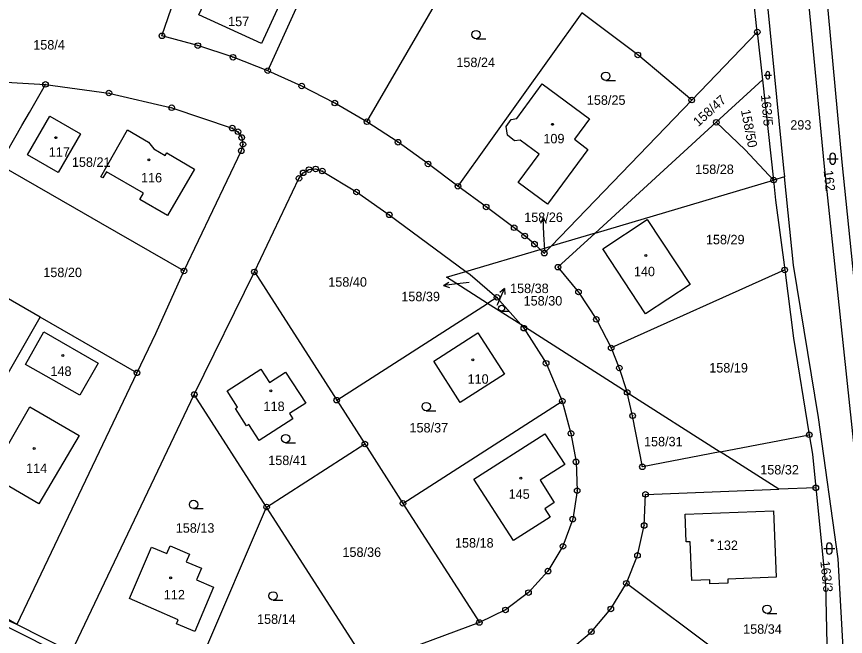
# Model space of a CAD drawing. Extents: x -779723 to -777378, y -1011169 to -1009297.
# Drawn here: x -779372 to -779222.9, y -1010124.4 to -1010012.9 of the extents above; entities that cross this region are included whole.
import ezdxf

# ---------------------------------------------------------------- set-up
doc = ezdxf.new("R2010")
doc.units = 0
for name, color, linetype in [('Hranice parcel', 7, 'Continuous'), ('Parcelní čísla', 7, 'Continuous'), ('Pop  PČ popisy', 7, 'Continuous'), ('Věcná břemena k části', 7, 'Continuous'), ('Značky bodu BP', 7, 'Continuous'), ('Značky budov', 7, 'Continuous'), ('Značky kultur', 7, 'Continuous')]:
    doc.layers.add(name, color=color, linetype=linetype)

msp = doc.modelspace()

# ---------------------------------------------------------------- linework, layer by layer
at = {"layer": 'Hranice parcel'}
for p, q in [((-779238.78, -1010015.64), (-779243.85, -1009969.77)), ((-779326.85, -1010022.6), (-779312.49, -1009991.16)), ((-779309, -1010031.79), (-779290.22, -1009999.35)), ((-779270.32, -1010012.18), (-779292.64, -1010043.39)), ((-779250.57, -1010027.88), (-779238.78, -1010015.64)), ((-779238.78, -1010015.64), (-779237.83, -1010024.25)), ((-779246.15, -1010031.88), (-779237.83, -1010024.25)), ((-779237.83, -1010024.25), (-779235.83, -1010042.28)), ((-779275.87, -1010054.16), (-779250.57, -1010027.88)), ((-779246.15, -1010031.88), (-779267.94, -1010051.81)), ((-779240.94, -1010036.84), (-779246.15, -1010031.88)), ((-779235.83, -1010042.28), (-779240.94, -1010036.84)), ((-779233.9, -1010041.71), (-779235.83, -1010042.28)), ((-779267.94, -1010051.81), (-779235.83, -1010042.28)), ((-779304.98, -1010048.53), (-779291.21, -1010058.71)), ((-779267.94, -1010051.81), (-779275.87, -1010054.16)), ((-779267.94, -1010051.81), (-779274.64, -1010057.94)), ((-779277.83, -1010054.74), (-779278.85, -1010053.8)), ((-779291.21, -1010058.71), (-779277.83, -1010054.74)), ((-779277.83, -1010054.74), (-779275.87, -1010054.16)), ((-779367.78, -1010066.96), (-779385.17, -1010056.96)), ((-779340.06, -1010080.85), (-779329.26, -1010058.8)), ((-779329.26, -1010058.8), (-779314.44, -1010081.88)), ((-779291.21, -1010058.71), (-779290.44, -1010059.28)), ((-779290.44, -1010059.28), (-779285.62, -1010063.38)), ((-779233.85, -1010058.45), (-779265.07, -1010072.49)), ((-779285.62, -1010063.38), (-779287.31, -1010064.46)), ((-779285.62, -1010063.38), (-779281.34, -1010068.27)), ((-779314.44, -1010081.88), (-779287.31, -1010064.46)), ((-779281.34, -1010068.27), (-779287.31, -1010064.46)), ((-779392.71, -1010110.31), (-779367.78, -1010066.96)), ((-779350.39, -1010076.96), (-779367.78, -1010066.96)), ((-779262.19, -1010080.48), (-779281.34, -1010068.27)), ((-779281.34, -1010068.27), (-779280.77, -1010068.92)), ((-779262.23, -1010080.33), (-779262.19, -1010080.48)), ((-779261.21, -1010084.68), (-779262.19, -1010080.48)), ((-779262.19, -1010080.48), (-779245.44, -1010091.17)), ((-779327.06, -1010101.1), (-779340.06, -1010080.85)), ((-779314.44, -1010081.88), (-779309.39, -1010089.76)), ((-779302.53, -1010100.44), (-779273.87, -1010082.04)), ((-779259.45, -1010093.86), (-779261.21, -1010084.68)), ((-779245.44, -1010091.17), (-779229.43, -1010088.1)), ((-779327.06, -1010101.1), (-779309.39, -1010089.76)), ((-779309.39, -1010089.76), (-779302.53, -1010100.44)), ((-779245.44, -1010091.17), (-779259.45, -1010093.86)), ((-779234.88, -1010097.91), (-779245.44, -1010091.17)), ((-779258.88, -1010098.83), (-779234.88, -1010097.91)), ((-779228.25, -1010097.65), (-779234.88, -1010097.91)), ((-779342.01, -1010135.87), (-779327.06, -1010101.1)), ((-779310.76, -1010126.49), (-779327.06, -1010101.1)), ((-779302.53, -1010100.44), (-779288.77, -1010121.88)), ((-779262.32, -1010114.82), (-779225.9, -1010141.96))]:
    msp.add_line(p, q, dxfattribs=at)
for points in [[(-779229.16, -1009906.17), (-779234.8, -1009917.25), (-779223.59, -1010039.03), (-779218.82, -1010085.26), (-779212.16, -1010143.8)], [(-779230.18, -1009906.58), (-779238.1, -1009916.55), (-779233.71, -1009966.95), (-779226.79, -1010039.25), (-779219.75, -1010106.05), (-779218.61, -1010144.17)], [(-779241.08, -1009968.91), (-779234.07, -1010040.11), (-779233.9, -1010041.71)], [(-779326.85, -1010022.6), (-779333.1, -1010020.18), (-779339.43, -1010018.09), (-779345.89, -1010016.32), (-779340.12, -1009999.61)], [(-779336.09, -1010005.63), (-779324.79, -1010010.8), (-779327.97, -1010017.71), (-779339.22, -1010012.55), (-779336.09, -1010005.63)], [(-779250.57, -1010027.88), (-779260.26, -1010019.77), (-779270.32, -1010012.18)], [(-779421.04, -1010023.31), (-779418.36, -1010019.05), (-779416.21, -1010016.69), (-779413.4, -1010015.24), (-779410.26, -1010014.85), (-779407.15, -1010015.59), (-779397.45, -1010019.81), (-779391.16, -1010022.12), (-779384.71, -1010023.64), (-779378.05, -1010024.4), (-779366.83, -1010025.07)], [(-779309, -1010031.79), (-779314.79, -1010028.42), (-779320.74, -1010025.36), (-779326.85, -1010022.6)], [(-779375.15, -1010039.53), (-779371.1, -1010032.49), (-779369.72, -1010030.1), (-779366.83, -1010025.07)], [(-779366.83, -1010025.07), (-779355.43, -1010026.62), (-779344.13, -1010029.26), (-779333.23, -1010032.93), (-779332.22, -1010033.58), (-779331.53, -1010034.62), (-779331.32, -1010035.85), (-779331.61, -1010037.02), (-779341.93, -1010058.63)], [(-779282.46, -1010035.19), (-779283.73, -1010034.23), (-779283.96, -1010032.63), (-779283.04, -1010031.37), (-779282.06, -1010031.21), (-779277.45, -1010024.98), (-779268.99, -1010031.25), (-779271.67, -1010034.94), (-779269.29, -1010036.77), (-779276.53, -1010046.6), (-779281.78, -1010042.74), (-779278, -1010037.62), (-779281.44, -1010035.08), (-779282.46, -1010035.19)], [(-779370.06, -1010037.75), (-779366.05, -1010030.8), (-779360.55, -1010033.95), (-779364.55, -1010040.92), (-779370.06, -1010037.75)], [(-779292.64, -1010043.39), (-779298.01, -1010039.38), (-779303.4, -1010035.47), (-779309, -1010031.79)], [(-779349.23, -1010044.65), (-779355.87, -1010040.77), (-779356.52, -1010041.89), (-779356.91, -1010041.67), (-779352.07, -1010033.25), (-779348.33, -1010035.44), (-779347.35, -1010036.64), (-779345.3, -1010037.84), (-779345.02, -1010037.36), (-779340.01, -1010040.29), (-779344.91, -1010048.67), (-779349.88, -1010045.77), (-779349.23, -1010044.65)], [(-779341.93, -1010058.63), (-779356.91, -1010050.02), (-779361.56, -1010047.34), (-779375.15, -1010039.53)], [(-779329.26, -1010058.8), (-779321.24, -1010041.97), (-779320.47, -1010040.98), (-779319.43, -1010040.4), (-779318.23, -1010040.28), (-779317.04, -1010040.66), (-779310.89, -1010044.42), (-779304.98, -1010048.53)], [(-779222.02, -1010149.91), (-779224.22, -1010110.43), (-779227.75, -1010085.02), (-779232.26, -1010057.56), (-779233.9, -1010041.71)], [(-779278.85, -1010053.8), (-779280.61, -1010052.33), (-779282.51, -1010050.85), (-779287.56, -1010047.11), (-779292.64, -1010043.39)], [(-779235.83, -1010042.28), (-779235.48, -1010045.87), (-779233.85, -1010058.45)], [(-779250.85, -1010061.04), (-779258.86, -1010066.35), (-779266.57, -1010054.66), (-779258.57, -1010049.37), (-779250.85, -1010061.04)], [(-779277.83, -1010054.74), (-779277.09, -1010055.43), (-779275.87, -1010054.16)], [(-779274.64, -1010057.94), (-779270.95, -1010062.42), (-779267.73, -1010067.35), (-779265.07, -1010072.49)], [(-779341.93, -1010058.63), (-779347.05, -1010069.95), (-779350.39, -1010076.96)], [(-779287.31, -1010064.46), (-779294.7, -1010059.75), (-779291.21, -1010058.71)], [(-779233.85, -1010058.45), (-779232.26, -1010070.73), (-779229.43, -1010088.1)], [(-779367.14, -1010069.6), (-779357.34, -1010075.2), (-779360.65, -1010080.96), (-779370.44, -1010075.43), (-779367.14, -1010069.6)], [(-779296.99, -1010074.85), (-779289.06, -1010069.75), (-779284.27, -1010077.21), (-779292.21, -1010082.32), (-779296.99, -1010074.85)], [(-779280.77, -1010068.92), (-779276.77, -1010075.24), (-779273.87, -1010082.04)], [(-779265.07, -1010072.49), (-779263.6, -1010076.09), (-779262.23, -1010080.33)], [(-779350.39, -1010076.96), (-779371.98, -1010122.22), (-779390.82, -1010111.39), (-779391.69, -1010110.89), (-779392.71, -1010110.31)], [(-779328.11, -1010076.32), (-779326.54, -1010078.72), (-779323.64, -1010076.83), (-779320.02, -1010082.41), (-779322.93, -1010084.3), (-779322.31, -1010085.25), (-779328.37, -1010089.12), (-779330.27, -1010086.25), (-779330.69, -1010086.49), (-779332.67, -1010083.38), (-779332.28, -1010083.11), (-779334.15, -1010080.2), (-779328.11, -1010076.32)], [(-779342.01, -1010135.87), (-779346.4, -1010133.98), (-779347.32, -1010133.59), (-779362.17, -1010127.2), (-779340.06, -1010080.85)], [(-779273.87, -1010082.04), (-779272.31, -1010087.85), (-779271.38, -1010092.97), (-779271.18, -1010098.16), (-779271.98, -1010103.28), (-779273.75, -1010108.17), (-779276.44, -1010112.63), (-779279.93, -1010116.49), (-779284.08, -1010119.61), (-779288.77, -1010121.88)], [(-779368.02, -1010100.51), (-779376.78, -1010095.43), (-779369.65, -1010083.1), (-779360.78, -1010088.23), (-779368.02, -1010100.51)], [(-779289.75, -1010096.1), (-779276.98, -1010087.91), (-779273.41, -1010093.44), (-779277.86, -1010096.28), (-779275.33, -1010100.31), (-779276.97, -1010101.4), (-779276.04, -1010102.9), (-779282.66, -1010107.15), (-779289.75, -1010096.1)], [(-779229.43, -1010088.1), (-779228.86, -1010091.61), (-779228.25, -1010097.65)], [(-779228.25, -1010097.65), (-779226.51, -1010114.99), (-779225.9, -1010141.96)], [(-779262.32, -1010114.82), (-779260.32, -1010109.8), (-779259.13, -1010104.42), (-779258.88, -1010098.83)], [(-779235.38, -1010113.69), (-779244.08, -1010114.07), (-779244.05, -1010114.82), (-779247.31, -1010114.94), (-779247.33, -1010114.19), (-779250.56, -1010114.32), (-779250.87, -1010107.34), (-779251.58, -1010107.36), (-779251.76, -1010102.41), (-779235.86, -1010101.78), (-779235.38, -1010113.69)], [(-779343.25, -1010122.14), (-779342.99, -1010121.4), (-779351.7, -1010117.58), (-779347.76, -1010108.31), (-779345.01, -1010109.46), (-779344.43, -1010108.09), (-779340.92, -1010109.57), (-779341.5, -1010110.95), (-779338.78, -1010112.1), (-779339.67, -1010114.22), (-779336.61, -1010115.51), (-779339.97, -1010123.49), (-779343.25, -1010122.14)], [(-779282.4, -1010131.79), (-779277.41, -1010129.77), (-779272.77, -1010127.01), (-779268.62, -1010123.54), (-779265.13, -1010119.44), (-779262.32, -1010114.82)], [(-779288.77, -1010121.88), (-779301.33, -1010126.54), (-779304.94, -1010128.18), (-779308.3, -1010130.32)]]:
    msp.add_lwpolyline(points, dxfattribs=at)
at = {"layer": 'Pop  PČ popisy'}
for p, q in [((-779277.31, -1010049.08), (-779277.76, -1010050.11)), ((-779277.15, -1010052.08), (-779277.31, -1010049.08)), ((-779277.31, -1010049.08), (-779276.76, -1010050.06)), ((-779276.99, -1010054.84), (-779277.15, -1010052.08)), ((-779295.21, -1010061.22), (-779294.27, -1010060.62)), ((-779292.23, -1010060.91), (-779295.21, -1010061.22)), ((-779295.21, -1010061.22), (-779294.17, -1010061.62)), ((-779290.6, -1010060.73), (-779292.23, -1010060.91)), ((-779285.44, -1010064.52), (-779284.27, -1010061.76)), ((-779284.27, -1010061.76), (-779285.12, -1010062.48)), ((-779284.27, -1010061.76), (-779284.2, -1010062.88)), ((-779285.55, -1010064.78), (-779285.44, -1010064.52))]:
    msp.add_line(p, q, dxfattribs=at)
at = {"layer": 'Věcná břemena k části'}
for points in [[(-779374.62, -1010122.18), (-779362.56, -1010128.21)], [(-779362.17, -1010127.2), (-779371.98, -1010122.22), (-779374.14, -1010121.3)]]:
    msp.add_lwpolyline(points, dxfattribs=at)
at = {"layer": 'Značky bodu BP'}
for centre, radius in [((-779345.89, -1010016.32), 0.5), ((-779345.89, -1010016.32), 0.0303), ((-779238.78, -1010015.64), 0.5), ((-779238.78, -1010015.64), 0.0303), ((-779339.43, -1010018.09), 0.5), ((-779339.43, -1010018.09), 0.0303), ((-779260.26, -1010019.77), 0.5), ((-779333.1, -1010020.18), 0.5), ((-779333.1, -1010020.18), 0.0303), ((-779260.26, -1010019.77), 0.0303), ((-779326.85, -1010022.6), 0.5), ((-779326.85, -1010022.6), 0.0303), ((-779366.83, -1010025.07), 0.5), ((-779366.83, -1010025.07), 0.0303), ((-779320.74, -1010025.36), 0.5), ((-779320.74, -1010025.36), 0.0303), ((-779355.43, -1010026.62), 0.5), ((-779355.43, -1010026.62), 0.0303), ((-779314.79, -1010028.42), 0.5), ((-779314.79, -1010028.42), 0.0303), ((-779250.57, -1010027.88), 0.5), ((-779250.57, -1010027.88), 0.0303), ((-779344.13, -1010029.26), 0.5), ((-779344.13, -1010029.26), 0.0303), ((-779309, -1010031.79), 0.5), ((-779246.15, -1010031.88), 0.5), ((-779333.23, -1010032.93), 0.5), ((-779333.23, -1010032.93), 0.0303), ((-779309, -1010031.79), 0.0303), ((-779246.15, -1010031.88), 0.0303), ((-779332.22, -1010033.58), 0.5), ((-779332.22, -1010033.58), 0.0303), ((-779331.53, -1010034.62), 0.5), ((-779331.32, -1010035.85), 0.5), ((-779331.53, -1010034.62), 0.0303), ((-779331.32, -1010035.85), 0.0303), ((-779303.4, -1010035.47), 0.5), ((-779303.4, -1010035.47), 0.0303), ((-779331.61, -1010037.02), 0.5), ((-779331.61, -1010037.02), 0.0303), ((-779298.01, -1010039.38), 0.5), ((-779319.43, -1010040.4), 0.5), ((-779319.43, -1010040.4), 0.0303), ((-779318.23, -1010040.28), 0.5), ((-779318.23, -1010040.28), 0.0303), ((-779317.04, -1010040.66), 0.5), ((-779298.01, -1010039.38), 0.0303), ((-779321.24, -1010041.97), 0.5), ((-779321.24, -1010041.97), 0.0303), ((-779320.47, -1010040.98), 0.5), ((-779320.47, -1010040.98), 0.0303), ((-779317.04, -1010040.66), 0.0303), ((-779235.83, -1010042.28), 0.5), ((-779292.64, -1010043.39), 0.5), ((-779292.64, -1010043.39), 0.0303), ((-779235.83, -1010042.28), 0.0303), ((-779310.89, -1010044.42), 0.5), ((-779310.89, -1010044.42), 0.0303), ((-779287.56, -1010047.11), 0.5), ((-779287.56, -1010047.11), 0.0303), ((-779304.98, -1010048.53), 0.5), ((-779304.98, -1010048.53), 0.0303), ((-779282.51, -1010050.85), 0.5), ((-779282.51, -1010050.85), 0.0303), ((-779280.61, -1010052.33), 0.5), ((-779280.61, -1010052.33), 0.0303), ((-779278.85, -1010053.8), 0.5), ((-779278.85, -1010053.8), 0.0303), ((-779277.09, -1010055.43), 0.5), ((-779277.09, -1010055.43), 0.0303), ((-779341.93, -1010058.63), 0.5), ((-779329.26, -1010058.8), 0.5), ((-779274.64, -1010057.94), 0.5), ((-779274.64, -1010057.94), 0.0303), ((-779233.85, -1010058.45), 0.5), ((-779341.93, -1010058.63), 0.0303), ((-779329.26, -1010058.8), 0.0303), ((-779233.85, -1010058.45), 0.0303), ((-779270.95, -1010062.42), 0.5), ((-779270.95, -1010062.42), 0.0303), ((-779285.62, -1010063.38), 0.5), ((-779285.62, -1010063.38), 0.0303), ((-779267.73, -1010067.35), 0.5), ((-779280.77, -1010068.92), 0.5), ((-779267.73, -1010067.35), 0.0303), ((-779280.77, -1010068.92), 0.0303), ((-779265.07, -1010072.49), 0.5), ((-779265.07, -1010072.49), 0.0303), ((-779276.77, -1010075.24), 0.5), ((-779276.77, -1010075.24), 0.0303), ((-779263.6, -1010076.09), 0.5), ((-779263.6, -1010076.09), 0.0303), ((-779350.39, -1010076.96), 0.5), ((-779350.39, -1010076.96), 0.0303), ((-779340.06, -1010080.85), 0.5), ((-779262.19, -1010080.48), 0.5), ((-779262.19, -1010080.48), 0.0303), ((-779340.06, -1010080.85), 0.0303), ((-779314.44, -1010081.88), 0.5), ((-779314.44, -1010081.88), 0.0303), ((-779273.87, -1010082.04), 0.5), ((-779273.87, -1010082.04), 0.0303), ((-779261.21, -1010084.68), 0.5), ((-779261.21, -1010084.68), 0.0303), ((-779272.31, -1010087.85), 0.5), ((-779272.31, -1010087.85), 0.0303), ((-779229.43, -1010088.1), 0.5), ((-779229.43, -1010088.1), 0.0303), ((-779309.39, -1010089.76), 0.5), ((-779309.39, -1010089.76), 0.0303), ((-779271.38, -1010092.97), 0.5), ((-779271.38, -1010092.97), 0.0303), ((-779259.45, -1010093.86), 0.5), ((-779259.45, -1010093.86), 0.0303), ((-779271.18, -1010098.16), 0.5), ((-779271.18, -1010098.16), 0.0303), ((-779258.88, -1010098.83), 0.5), ((-779228.25, -1010097.65), 0.5), ((-779228.25, -1010097.65), 0.0303), ((-779302.53, -1010100.44), 0.5), ((-779258.88, -1010098.83), 0.0303), ((-779327.06, -1010101.1), 0.5), ((-779327.06, -1010101.1), 0.0303), ((-779302.53, -1010100.44), 0.0303), ((-779271.98, -1010103.28), 0.5), ((-779271.98, -1010103.28), 0.0303), ((-779259.13, -1010104.42), 0.5), ((-779259.13, -1010104.42), 0.0303), ((-779273.75, -1010108.17), 0.5), ((-779273.75, -1010108.17), 0.0303), ((-779260.32, -1010109.8), 0.5), ((-779260.32, -1010109.8), 0.0303), ((-779276.44, -1010112.63), 0.5), ((-779276.44, -1010112.63), 0.0303), ((-779262.32, -1010114.82), 0.5), ((-779262.32, -1010114.82), 0.0303), ((-779279.93, -1010116.49), 0.5), ((-779279.93, -1010116.49), 0.0303), ((-779284.08, -1010119.61), 0.5), ((-779265.13, -1010119.44), 0.5), ((-779265.13, -1010119.44), 0.0303), ((-779284.08, -1010119.61), 0.0303), ((-779288.77, -1010121.88), 0.5), ((-779288.77, -1010121.88), 0.0303), ((-779268.62, -1010123.54), 0.5), ((-779268.62, -1010123.54), 0.0303)]:
    msp.add_circle(centre, radius, dxfattribs=at)
at = {"layer": 'Značky budov'}
for centre in [(-779275.62, -1010032.25), (-779365, -1010034.65), (-779348.22, -1010038.63), (-779258.83, -1010055.84), (-779363.72, -1010073.83), (-779289.95, -1010074.61), (-779326.28, -1010080.19), (-779368.89, -1010090.59), (-779281.3, -1010095.89), (-779246.9, -1010107.14), (-779344.32, -1010113.85)]:
    msp.add_circle(centre, 0.175, dxfattribs=at)
at = {"layer": 'Značky kultur'}
for p, q in [((-779289.38, -1010016.86), (-779287.63, -1010016.86)), ((-779237.55, -1010023.42), (-779236.21, -1010023.42)), ((-779237.21, -1010023.09), (-779237.21, -1010023.76)), ((-779236.55, -1010023.76), (-779236.55, -1010023.09)), ((-779266.03, -1010024.35), (-779264.28, -1010024.35)), ((-779226.22, -1010038.43), (-779224.22, -1010038.43)), ((-779225.72, -1010037.93), (-779225.72, -1010038.93)), ((-779224.72, -1010038.93), (-779224.72, -1010037.93)), ((-779284.79, -1010065.87), (-779283.53, -1010065.87)), ((-779298.34, -1010083.78), (-779296.59, -1010083.78)), ((-779323.63, -1010089.54), (-779321.88, -1010089.54)), ((-779340.2, -1010101.38), (-779338.45, -1010101.38)), ((-779226.83, -1010108.58), (-779224.83, -1010108.58)), ((-779226.33, -1010108.08), (-779226.33, -1010109.08)), ((-779225.33, -1010109.08), (-779225.33, -1010108.08)), ((-779325.88, -1010117.84), (-779324.13, -1010117.84)), ((-779237.01, -1010120.23), (-779235.26, -1010120.23))]:
    msp.add_line(p, q, dxfattribs=at)
for centre, radius in [((-779289.38, -1010016.11), 0.75), ((-779266.03, -1010023.6), 0.75), ((-779284.78, -1010065.33), 0.54), ((-779298.34, -1010083.03), 0.75), ((-779323.63, -1010088.79), 0.75), ((-779340.2, -1010100.63), 0.75), ((-779325.88, -1010117.09), 0.75), ((-779237.01, -1010119.48), 0.75)]:
    msp.add_circle(centre, radius, dxfattribs=at)
for centre, radius, start, end in [((-779236.88, -1010023.09), 0.335, 0, 180), ((-779236.88, -1010023.76), 0.335, 180, 359.9879), ((-779225.22, -1010037.93), 0.5, 0, 180), ((-779225.22, -1010038.93), 0.5, 180, 359.9879), ((-779225.83, -1010108.08), 0.5, 0, 180), ((-779225.83, -1010109.08), 0.5, 180, 359.9879)]:
    msp.add_arc(centre, radius, start, end, dxfattribs=at)

# ---------------------------------------------------------------- texts
at = {"layer": 'Parcelní čísla'}
for s, p in [('157', (-779333.98, -1010014.59)), ('158/4', (-779369.04, -1010018.8)), ('158/24', (-779292.92, -1010021.95)), ('158/25', (-779269.44, -1010028.74)), ('293', (-779232.84, -1010033.21)), ('109', (-779277.26, -1010035.67)), ('117', (-779366.24, -1010038.08)), ('158/21', (-779362.09, -1010039.9)), ('158/28', (-779249.95, -1010041.19)), ('116', (-779349.65, -1010042.7)), ('158/26', (-779280.71, -1010049.82)), ('158/29', (-779248.02, -1010053.83)), ('158/20', (-779367.23, -1010059.74)), ('140', (-779260.98, -1010059.58)), ('158/40', (-779315.96, -1010061.46)), ('158/38', (-779283.26, -1010062.61)), ('158/39', (-779302.82, -1010064.08)), ('158/30', (-779280.82, -1010064.85)), ('148', (-779365.95, -1010077.51)), ('158/19', (-779247.42, -1010076.9)), ('110', (-779290.9, -1010078.92)), ('118', (-779327.61, -1010083.83)), ('158/37', (-779301.35, -1010087.68)), ('158/31', (-779259.16, -1010090.18)), ('158/41', (-779326.76, -1010093.55)), ('114', (-779370.33, -1010094.97)), ('158/32', (-779238.25, -1010095.24)), ('145', (-779283.51, -1010099.62)), ('158/13', (-779343.4, -1010105.72)), ('158/18', (-779293.17, -1010108.4)), ('132', (-779246.05, -1010108.83)), ('158/36', (-779313.41, -1010110.07)), ('112', (-779345.55, -1010117.72)), ('158/14', (-779328.78, -1010122.12)), ('158/34', (-779241.32, -1010123.9))]:
    msp.add_text(s, height=1.7, dxfattribs=at).set_placement(p)
for s, rotation, p in [('158/47', 42, (-779249.39, -1010032.76)), ('163/5', 275, (-779238.12, -1010026.96)), ('158/50', 281, (-779241.73, -1010029.73)), ('162', 276, (-779226.85, -1010040.59)), ('163/3', 276, (-779227.44, -1010110.86))]:
    msp.add_text(s, height=1.7, rotation=rotation, dxfattribs=at).set_placement(p)

doc.saveas('drawing.dxf')
